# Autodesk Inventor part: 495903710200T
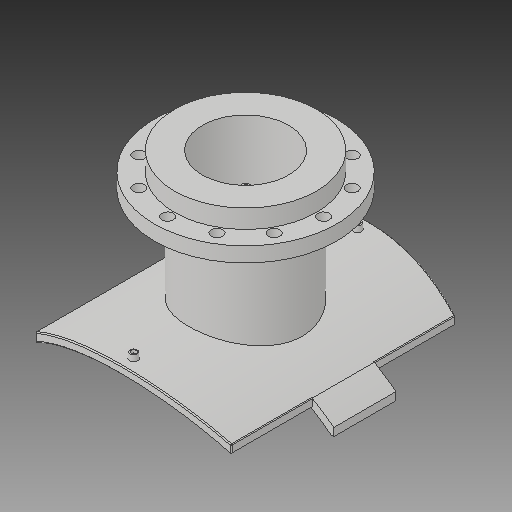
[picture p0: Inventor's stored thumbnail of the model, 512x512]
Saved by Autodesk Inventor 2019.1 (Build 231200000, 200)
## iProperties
Created: 2017-10
Part Number: 495903710200T
Material: Generic
Description: PLASSON FLANGED BRANCH SADDLE 710X200
Document SubType Name: Modeling
Designer: KIM
Mass: 2339.99 g
Surface Area: 3251.55 cm^2
Volume: 2339.99 cm^3
Density: 1 g/cm^3
Appearance: Default
Author: KIM
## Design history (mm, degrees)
derived "495904_495903.ipt"
feature "Solid1::495904_495903.ipt"
feature "Solid2::495904_495903.ipt"
tag "TaggingFeature1"
body "Solid1"
other parameters: "d1" = 15, "d2" = 369, "d4" = 0, "d6" = 117.5, "d7" = 0, "d12" = 380.6, "d13" = 14, "d14" = 211.5, "d16" = 5 deg, "d18" = 4, "d19" = 14, "d20" = 0, "d21" = 3, "d22" = 0, "d36" = 211.5, "d38" = 0, "d39" = 2, "d41" = 163, "d42" = 268, "d43" = 344, "d46" = 214.4, "d47" = 16, "d48" = 10.4, "d49" = 175, "d51" = 724.2, "d53" = 0, "d54" = 22, "d55" = 147.5, "d57" = 0, "d59" = 360 deg, "d61" = 28, "d63" = 0, "d67" = 15, "d68" = 125, "d70" = 0, "d71" = 2, "d_1" = 268, "x_" = 15, "D_" = 16, "DN_" = 163, "D_1" = 344, "t_" = 28, "s_" = 22, "Dp_" = 295
